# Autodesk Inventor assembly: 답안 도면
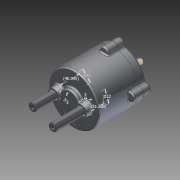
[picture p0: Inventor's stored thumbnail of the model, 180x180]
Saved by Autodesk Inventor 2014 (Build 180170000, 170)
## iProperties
Created: 2015-02
Part Number: 답안 도면
Document SubType Name: Assembly
Designer: basic
Mass: 1967.35 g
Surface Area: 1692.8 cm^2
Volume: 412.892 cm^3
Density: 4.76479 g/cm^3
Author: basic
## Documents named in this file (13)
- C:\Users\basic\Desktop\350207V1006\답안 도면.iam
- C:\Users\basic\Desktop\350207V1006\몸체.ipt
- C:\Users\basic\Desktop\350207V1006\M5x0.5x20.ipt
- C:\Users\basic\Desktop\350207V1006\멈춤링 10 x 1.ipt
- C:\Users\basic\Desktop\350207V1006\멈춤링 22 x 1.2.ipt
- C:\Users\basic\Desktop\350207V1006\메인 축.ipt
- C:\Users\basic\Desktop\350207V1006\베어링 NA 4900.ipt
- C:\Users\basic\Desktop\350207V1006\슬라이드 축.ipt
- C:\Users\basic\Desktop\350207V1006\오일실.ipt
- C:\Users\basic\Desktop\350207V1006\커버.ipt
- C:\Users\basic\Desktop\350207V1006\판캠.ipt
- C:\Users\basic\Desktop\350207V1006\가변스프링1.ipt
- C:\Users\basic\Desktop\350207V1006\가변스프링2.ipt
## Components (6 placed, 3 different names)
1. 가변스프링1:1
2. 가변스프링2:1
3. M5x0.5x20:1
4. M5x0.5x20:2
5. M5x0.5x20:3
6. M5x0.5x20:4
